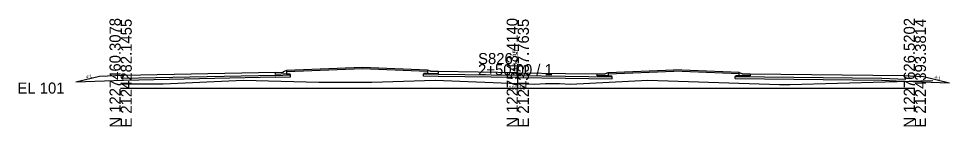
# Model space of a CAD drawing. Extents: x 2118382 to 2118616, y 1213030 to 1222057.
# Drawn here: x 2118381.9 to 2118616.3, y 1213030.1 to 1213057.3 of the extents above; entities that cross this region are included whole.
import ezdxf

# ---------------------------------------------------------------- set-up
doc = ezdxf.new("R2010")
doc.units = 0
for name, color, linetype in [('TS_CURB_GUTTER', 7, 'Continuous'), ('XS_CELL', 7, 'Continuous'), ('XS_P_CONCRETE', 7, 'Continuous'), ('XS_P_FINISHED_GRADE', 7, 'Continuous'), ('XS_P_FINISHED_GRADE_ELEV_TX', 7, 'Continuous'), ('XS_P_SUBGRADE_GRANULAR', 7, 'Continuous'), ('XS_P_SUBGRADE_GRANULAR_B', 7, 'Continuous'), ('XS_P_SUBGRADE_PAVEMENT', 7, 'Continuous'), ('XS_P_TX_FS_BS', 7, 'Continuous'), ('XS_X_GROUND', 7, 'Continuous'), ('XS_X_GROUND_TX', 7, 'Continuous')]:
    doc.layers.add(name, color=color, linetype=linetype)

msp = doc.modelspace()

# ---------------------------------------------------------------- linework, layer by layer
at = {"layer": 'TS_CURB_GUTTER'}
for points in [[(2118449.34, 1213044.19), (2118449.36, 1213043.37), (2118446.61, 1213043.26), (2118446.59, 1213043.76), (2118448.59, 1213043.84), (2118448.59, 1213043.86), (2118448.59, 1213043.89), (2118448.6, 1213043.91), (2118448.61, 1213043.93), (2118448.64, 1213043.95), (2118449.32, 1213044.2), (2118449.33, 1213044.2), (2118449.33, 1213044.2), (2118449.33, 1213044.2), (2118449.34, 1213044.19), (2118449.34, 1213044.19)], [(2118484.85, 1213044.3), (2118484.85, 1213043.48), (2118487.6, 1213043.44), (2118487.6, 1213043.94), (2118485.6, 1213043.97), (2118485.6, 1213043.99), (2118485.6, 1213044.02), (2118485.59, 1213044.04), (2118485.57, 1213044.06), (2118485.54, 1213044.07), (2118484.86, 1213044.31), (2118484.86, 1213044.31), (2118484.85, 1213044.31), (2118484.85, 1213044.31), (2118484.85, 1213044.3), (2118484.85, 1213044.3)], [(2118530.37, 1213043.7), (2118530.35, 1213042.89), (2118527.6, 1213042.92), (2118527.6, 1213043.42), (2118529.6, 1213043.4), (2118529.6, 1213043.42), (2118529.61, 1213043.44), (2118529.62, 1213043.46), (2118529.63, 1213043.48), (2118529.66, 1213043.5), (2118530.35, 1213043.71), (2118530.36, 1213043.72), (2118530.36, 1213043.71), (2118530.37, 1213043.71), (2118530.37, 1213043.71), (2118530.37, 1213043.7)], [(2118566.12, 1213043.35), (2118566.11, 1213042.85), (2118563.36, 1213042.89), (2118563.36, 1213043.7), (2118563.36, 1213043.71), (2118563.36, 1213043.71), (2118563.37, 1213043.72), (2118563.37, 1213043.71), (2118564.06, 1213043.48), (2118564.09, 1213043.46), (2118564.11, 1213043.43), (2118564.12, 1213043.4), (2118564.12, 1213043.38), (2118566.12, 1213043.35)]]:
    msp.add_lwpolyline(points, dxfattribs=at)
at = {"layer": 'XS_CELL'}
for p, q in [((2118507.6, 1213039.8), (2118507.6, 1213045.84)), ((2118407.6, 1213039.8), (2118507.6, 1213039.8)), ((2118507.6, 1213039.8), (2118607.6, 1213039.8))]:
    msp.add_line(p, q, dxfattribs=at)
at = {"layer": 'XS_P_CONCRETE'}
for p, q in [((2118468.47, 1213044.63), (2118449.34, 1213043.87)), ((2118484.85, 1213043.98), (2118468.47, 1213044.63)), ((2118530.36, 1213043.38), (2118546.86, 1213044.04)), ((2118563.36, 1213043.38), (2118546.86, 1213044.04))]:
    msp.add_line(p, q, dxfattribs=at)
at = {"layer": 'XS_P_FINISHED_GRADE'}
for p, q in [((2118468.47, 1213044.96), (2118449.33, 1213044.2)), ((2118484.85, 1213044.31), (2118468.47, 1213044.96)), ((2118402.28, 1213042.76), (2118396.32, 1213041.27)), ((2118408.28, 1213043), (2118402.28, 1213042.76)), ((2118446.59, 1213043.76), (2118408.28, 1213043)), ((2118507.6, 1213043.65), (2118487.6, 1213043.94)), ((2118507.6, 1213043.65), (2118519.6, 1213043.51)), ((2118519.6, 1213043.51), (2118527.6, 1213043.42)), ((2118530.36, 1213043.72), (2118546.86, 1213044.38)), ((2118563.37, 1213043.71), (2118546.86, 1213044.38)), ((2118566.12, 1213043.35), (2118604.76, 1213042.95)), ((2118604.76, 1213042.95), (2118609.76, 1213042.75)), ((2118609.76, 1213042.75), (2118616.29, 1213041.12))]:
    msp.add_line(p, q, dxfattribs=at)
at = {"layer": 'XS_P_SUBGRADE_GRANULAR'}
for p, q in [((2118446.61, 1213042.51), (2118408.3, 1213041.75)), ((2118446.61, 1213042.51), (2118450.36, 1213042.66)), ((2118450.36, 1213042.66), (2118450.36, 1213043.16)), ((2118483.85, 1213042.79), (2118483.85, 1213043.29)), ((2118487.59, 1213043.23), (2118483.85, 1213043.29)), ((2118487.59, 1213042.73), (2118483.85, 1213042.79)), ((2118507.59, 1213042.44), (2118487.59, 1213042.73)), ((2118531.34, 1213042.17), (2118531.34, 1213042.67)), ((2118562.36, 1213042.23), (2118562.36, 1213042.73)), ((2118408.3, 1213041.75), (2118396.32, 1213041.27)), ((2118507.59, 1213042.44), (2118519.59, 1213042.3)), ((2118519.59, 1213042.3), (2118531.34, 1213042.17)), ((2118562.36, 1213042.23), (2118599.31, 1213041.8)), ((2118599.31, 1213041.8), (2118604.71, 1213041.58)), ((2118604.71, 1213041.58), (2118616.29, 1213041.12))]:
    msp.add_line(p, q, dxfattribs=at)
at = {"layer": 'XS_P_SUBGRADE_GRANULAR_B'}
for p, q in [((2118449.36, 1213043.37), (2118450.22, 1213043.41)), ((2118450.36, 1213043.16), (2118450.22, 1213043.41)), ((2118483.85, 1213043.29), (2118483.97, 1213043.49)), ((2118484.85, 1213043.48), (2118483.97, 1213043.49)), ((2118530.35, 1213042.89), (2118531.22, 1213042.88)), ((2118531.34, 1213042.67), (2118531.22, 1213042.88)), ((2118562.36, 1213042.73), (2118562.45, 1213042.89)), ((2118563.36, 1213042.89), (2118562.45, 1213042.89))]:
    msp.add_line(p, q, dxfattribs=at)
at = {"layer": 'XS_P_SUBGRADE_PAVEMENT'}
for p, q in [((2118446.6, 1213043.01), (2118407.84, 1213042.24)), ((2118408.28, 1213043), (2118407.84, 1213042.24)), ((2118446.6, 1213043.01), (2118450.36, 1213043.16)), ((2118507.59, 1213042.94), (2118487.59, 1213043.23)), ((2118507.59, 1213042.94), (2118519.59, 1213042.8)), ((2118519.59, 1213042.8), (2118531.34, 1213042.67)), ((2118562.36, 1213042.73), (2118599.31, 1213042.3)), ((2118604.76, 1213042.95), (2118605.28, 1213042.06)), ((2118599.31, 1213042.3), (2118605.28, 1213042.06))]:
    msp.add_line(p, q, dxfattribs=at)
at = {"layer": 'XS_X_GROUND'}
for p, q in [((2118407.6, 1213040.83), (2118416.46, 1213040.86)), ((2118416.46, 1213040.86), (2118418.34, 1213040.86)), ((2118418.34, 1213040.86), (2118438.51, 1213041.82)), ((2118438.51, 1213041.82), (2118457.47, 1213041.29)), ((2118457.47, 1213041.29), (2118470.86, 1213041.26)), ((2118470.86, 1213041.26), (2118486.81, 1213041.79)), ((2118486.81, 1213041.79), (2118507.6, 1213040.96)), ((2118507.6, 1213040.96), (2118511.91, 1213040.79)), ((2118511.91, 1213040.79), (2118514.56, 1213040.94)), ((2118514.56, 1213040.94), (2118516.39, 1213040.98)), ((2118516.39, 1213040.98), (2118518.12, 1213040.95)), ((2118518.12, 1213040.95), (2118520.86, 1213040.78)), ((2118520.86, 1213040.78), (2118540.32, 1213041.77)), ((2118540.32, 1213041.77), (2118573.53, 1213040.67)), ((2118573.53, 1213040.67), (2118574.38, 1213040.74)), ((2118574.38, 1213040.74), (2118576.07, 1213040.66)), ((2118576.07, 1213040.66), (2118612.15, 1213041.7))]:
    msp.add_line(p, q, dxfattribs=at)

# ---------------------------------------------------------------- texts
at = {"layer": 'XS_CELL'}
for s, p in [('N 1227460.3078', (2118407.6, 1213029.8)), ('E 2124282.1455', (2118410.4, 1213029.8)), ('N 1227543.4140', (2118507.6, 1213029.8)), ('E 2124337.7635', (2118510.4, 1213029.8)), ('N 1227626.5202', (2118607.6, 1213029.8)), ('E 2124393.3814', (2118610.4, 1213029.8))]:
    msp.add_text(s, height=2.8, rotation=90, dxfattribs=at).set_placement(p)
for s, p in [('S826', (2118497.6, 1213045.84)), ('2+50.00 / 1', (2118497.6, 1213043.04)), ('EL 101', (2118381.6, 1213038.4))]:
    msp.add_text(s, height=2.8, dxfattribs=at).set_placement(p)
at = {"layer": 'XS_P_FINISHED_GRADE_ELEV_TX'}
msp.add_text(' 104.85', height=1.25, rotation=90, dxfattribs=at).set_placement((2118507.6, 1213043.73))
at = {"layer": 'XS_P_TX_FS_BS'}
for rotation, p in [(14.0362, (2118398.96, 1213042.12)), (345.9638, (2118612.47, 1213042.22))]:
    msp.add_text('4:1', height=0.8, rotation=rotation, dxfattribs=at).set_placement(p)
at = {"layer": 'XS_X_GROUND_TX'}
msp.add_text('102.16', height=1, dxfattribs=at).set_placement((2118505.29, 1213039.37))

doc.saveas('drawing.dxf')
